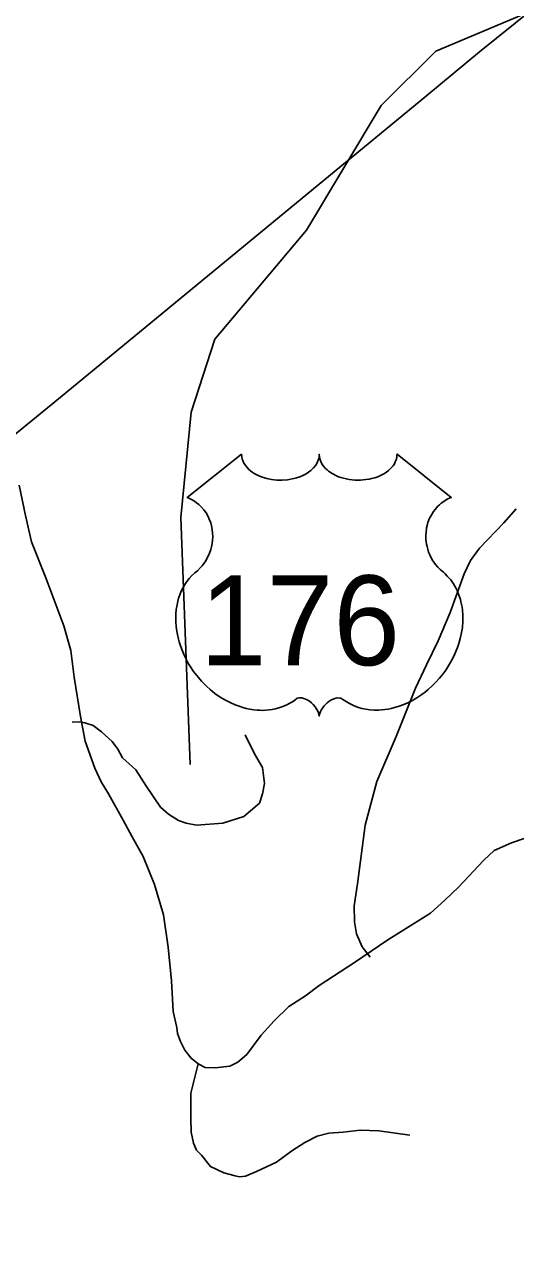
# Model space of a CAD drawing. Extents: x 990631 to 1056237, y 535999 to 585651.
# Drawn here: x 1003300 to 1004463, y 554837 to 557741 of the extents above; entities that cross this region are included whole.
import ezdxf

# ---------------------------------------------------------------- set-up
doc = ezdxf.new("R2010")
doc.units = 0
for name, color, linetype in [('Exist Boundary Political City Limit New', 7, 'Continuous'), ('Exist Hydrographic Creek Single Shore', 7, 'Continuous'), ('Exist Road Non-System Type 51', 7, 'Continuous'), ('Exist Road Primary US Attributed', 7, 'Continuous'), ('Exist Road Primary US Shield CELL', 7, 'Continuous'), ('Exist Road Primary US Shield Number Label', 7, 'Continuous')]:
    doc.layers.add(name, color=color, linetype=linetype)

msp = doc.modelspace()

# ---------------------------------------------------------------- linework, layer by layer
at = {"layer": 'Exist Boundary Political City Limit New'}
msp.add_lwpolyline([(1001301.9, 554778.2), (1001438.1, 555089.9), (1001470.1, 555241.1), (1001552.6, 555419.9), (1001735.9, 555580.4), (1002552.2, 556178.9), (1003398, 556869.2), (1004252.8, 557573.4), (1004377.7, 557676.6), (1005330.6, 558443.4), (1004972.3, 558948.1), (1005102.7, 559003.6), (1005249.3, 559124.2), (1005422, 559391.5), (1005487.1, 559453.4), (1005757.6, 559769.7), (1005899.7, 560044.6), (1005994.2, 560116.4), (1006062.6, 560031.6), (1006189.7, 560148.9), (1006241.8, 560201.1), (1006333.1, 560158.8), (1006620.9, 560644.3), (1006721.9, 560751.9)], dxfattribs=at)
at = {"layer": 'Exist Hydrographic Creek Single Shore'}
msp.add_lwpolyline([(1003692.1, 555990), (1003670, 556574.5), (1003695, 556823.4), (1003750.7, 556996.3), (1003967.8, 557254.5), (1004144.4, 557549.5), (1004273.7, 557678.2), (1005009.6, 557988.3), (1005177.7, 558030.8), (1005469.7, 558038), (1005563.7, 558101.8), (1005642.1, 558198.7), (1005936.2, 558265), (1006174.3, 558407.8), (1006530.5, 558338.3), (1006819.2, 557994.4), (1006909.7, 557956.5), (1007060.2, 557969.9), (1007340.5, 558125.1), (1007600, 558402), (1007761.6, 558497.2), (1008013.6, 558676.5), (1008218.4, 558820.1)], dxfattribs=at)
msp.add_lwpolyline([(1003692.1, 555990), (1003670, 556574.5), (1003695, 556823.4), (1003750.7, 556996.3), (1003967.8, 557254.5), (1004144.4, 557549.5), (1004273.7, 557678.2), (1005009.6, 557988.3), (1005177.7, 558030.8), (1005469.7, 558038), (1005563.7, 558101.8), (1005642.1, 558198.7), (1005936.2, 558265), (1006174.3, 558407.8), (1006530.5, 558338.3), (1006819.2, 557994.4), (1006909.7, 557956.5), (1007060.2, 557969.9), (1007340.5, 558125.1), (1007600, 558402), (1007761.6, 558497.2), (1008013.6, 558676.5), (1008218.4, 558820.1)], dxfattribs=at)
at = {"layer": 'Exist Road Non-System Type 51'}
for points in [[(1004464.2, 556594.9), (1004435.2, 556561.7), (1004377.1, 556501.6), (1004356.1, 556472.2), (1004341.1, 556440.7), (1004308.1, 556349.8), (1004279.7, 556282.7), (1004251.9, 556225.7), (1004226, 556170.4), (1004180.1, 556055.8), (1004134.5, 555949.3), (1004107, 555846.3), (1004088.4, 555706.8), (1004080.8, 555654.9), (1004081.4, 555616.9), (1004086.5, 555588.8), (1004099.4, 555558.3), (1004118.7, 555533.5)], [(1003822.1, 556059.9), (1003844.6, 556015), (1003863.5, 555982.4), (1003868.2, 555944.3), (1003863.5, 555920.4), (1003856.6, 555898.5), (1003819.7, 555866.5), (1003769.7, 555850.7), (1003707, 555846.3), (1003683.1, 555851), (1003664.5, 555856.9), (1003640.8, 555871.8), (1003622.3, 555888.5), (1003589, 555937.6), (1003563.6, 555977.1), (1003532.1, 556005.5), (1003520.7, 556025.9), (1003507.3, 556044.4), (1003482.1, 556067.1), (1003462.6, 556081.9), (1003442.7, 556088.5), (1003430.8, 556091), (1003412.8, 556089.5)], [(1003711, 555281.1), (1003693.7, 555211.6), (1003693.7, 555151.6), (1003694.7, 555119.5), (1003699.8, 555093.2), (1003707.2, 555077.1), (1003718.8, 555064.6), (1003740, 555037.8), (1003771.6, 555022.8), (1003799.2, 555016), (1003809.2, 555013.6), (1003823.2, 555015.1), (1003849.6, 555026.2), (1003896.3, 555048.6), (1003933.3, 555075.5), (1003964.1, 555094.5), (1003992.6, 555109.5), (1004020.7, 555116.6), (1004054.8, 555119.5), (1004095.1, 555124.1), (1004139.1, 555122.6), (1004212.7, 555112.1)]]:
    msp.add_lwpolyline(points, dxfattribs=at)
at = {"layer": 'Exist Road Primary US Attributed'}
msp.add_lwpolyline([(1003287.2, 556650.9), (1003302.1, 556579.2), (1003316.3, 556516.7), (1003350.4, 556431.7), (1003393.4, 556317.6), (1003410, 556259.7), (1003417.9, 556196.1), (1003432.9, 556103), (1003443.4, 556045.1), (1003466.2, 555980.6), (1003481.1, 555949), (1003498.8, 555920.4), (1003533.7, 555857.7), (1003554.8, 555818.2), (1003581.1, 555771.7), (1003608.1, 555705.9), (1003628.8, 555633.9), (1003639.9, 555557.6), (1003648.2, 555477.6), (1003652.2, 555405.1), (1003660.9, 555366.9), (1003662.4, 555352.9), (1003669.7, 555333.8), (1003679.4, 555313.6), (1003694.3, 555294.3), (1003711, 555281.1), (1003727.8, 555272.5), (1003751.8, 555271.6), (1003786.4, 555275.6), (1003804.8, 555285.1), (1003826.8, 555303.5), (1003860.1, 555349.2), (1003890.8, 555382.5), (1003925.9, 555416.7), (1003965.4, 555442.2), (1003997.8, 555466.3), (1004081.2, 555520.7), (1004160.1, 555574.3), (1004261, 555637.5), (1004295.2, 555668.2), (1004327.7, 555699.3), (1004387.4, 555763.4), (1004411.9, 555786.2), (1004453.2, 555804.6), (1004483, 555814.3)], dxfattribs=at)
at = {"layer": 'Exist Road Primary US Shield CELL'}
msp.add_lwpolyline([(1003814, 556724), (1003814.4, 556718.6), (1003815.7, 556712.3), (1003816.7, 556709.1), (1003819.6, 556702.8), (1003824.5, 556695.5), (1003831.3, 556688.3), (1003839, 556681.9), (1003844.1, 556678.6), (1003852.9, 556673.9), (1003862.8, 556669.7), (1003873.9, 556666.5), (1003885.2, 556664.2), (1003897.6, 556662.9), (1003909.8, 556662.6), (1003923.1, 556663.6), (1003937.6, 556666.4), (1003944.4, 556668.2), (1003951.9, 556670.8), (1003958.9, 556673.7), (1003966.6, 556677.8), (1003972.7, 556681.7), (1003977.6, 556685.2), (1003984.4, 556691.7), (1003989.8, 556698.5), (1003992.1, 556702.3), (1003994.1, 556706), (1003996.8, 556713.7), (1003997.5, 556717.1), (1003998.1, 556724.2), (1003998.5, 556718.3), (1003999.1, 556714.5), (1004000.1, 556710.9), (1004001.6, 556707), (1004004.4, 556701.6), (1004007.4, 556697), (1004013.1, 556690.2), (1004016.7, 556686.9), (1004020, 556684.2), (1004028.7, 556678.2), (1004038.9, 556673.1), (1004043.9, 556670.9), (1004049.1, 556669), (1004055.6, 556667.1), (1004062.4, 556665.5), (1004069.1, 556664.3), (1004075.9, 556663.3), (1004082.9, 556662.8), (1004088.6, 556662.6), (1004095.6, 556662.7), (1004102, 556663.1), (1004108.6, 556663.9), (1004115.9, 556665.1), (1004121.8, 556666.4), (1004129.5, 556668.4), (1004136.5, 556670.9), (1004142.7, 556673.6), (1004150.6, 556677.8), (1004157.1, 556681.8), (1004161.8, 556685.6), (1004167.4, 556690.8), (1004172.7, 556696.9), (1004175.9, 556701.4), (1004178.1, 556706), (1004180.1, 556710.9), (1004181.4, 556716.1), (1004182, 556720.5), (1004182.1, 556724.4), (1004310.7, 556621.9), (1004307.7, 556620.8), (1004300.7, 556617.4), (1004295.1, 556614.1), (1004286.3, 556607.9), (1004282.5, 556604.4), (1004278.7, 556600.9), (1004275.2, 556597.1), (1004272.1, 556593.5), (1004268.4, 556588.3), (1004265.1, 556583.2), (1004261.8, 556577.5), (1004259.4, 556572.5), (1004255.4, 556562.2), (1004253.5, 556555.7), (1004252.3, 556550.1), (1004250.8, 556538.6), (1004250.4, 556533.2), (1004250.4, 556527.8), (1004250.7, 556522.1), (1004251.3, 556516.6), (1004252.3, 556510.9), (1004253.2, 556505.9), (1004254.8, 556499.7), (1004257, 556492.6), (1004259.9, 556485.7), (1004265.7, 556474.5), (1004273.3, 556463.1), (1004278.7, 556456.7), (1004284, 556451.3), (1004291.9, 556444.6), (1004296.2, 556440.8), (1004301.2, 556435.8), (1004309.2, 556426.5), (1004312.5, 556422.1), (1004315.8, 556417.1), (1004318.8, 556412), (1004321.9, 556406.6), (1004324.3, 556401.8), (1004328.8, 556390.8), (1004332.1, 556380), (1004333.6, 556374.4), (1004336, 556361.8), (1004336.9, 556355.6), (1004337.9, 556343.3), (1004338, 556328.4), (1004336.8, 556314.2), (1004334.2, 556297.8), (1004332, 556287.9), (1004328.6, 556276.4), (1004325.3, 556266.4), (1004319.4, 556251.8), (1004314.2, 556241.1), (1004307.5, 556228.7), (1004302.8, 556221.2), (1004297.4, 556213.1), (1004290.7, 556203.8), (1004282.8, 556194), (1004273.3, 556183.5), (1004265.6, 556175.9), (1004255.6, 556166.9), (1004249.5, 556161.9), (1004240.9, 556155.4), (1004229, 556147.5), (1004217.3, 556140.7), (1004207.4, 556135.6), (1004198.6, 556131.8), (1004187.2, 556127.5), (1004168.2, 556122.2), (1004161.3, 556120.8), (1004153.1, 556119.6), (1004145.4, 556118.8), (1004138, 556118.4), (1004127.9, 556118.4), (1004118, 556119.1), (1004108.6, 556120.5), (1004098.8, 556122.5), (1004088.5, 556125.6), (1004079.2, 556129.2), (1004069.8, 556133.9), (1004053.9, 556143.9), (1004049.3, 556146.3), (1004046.7, 556147), (1004040.6, 556147.3), (1004034.8, 556146.1), (1004028.9, 556143.7), (1004025.3, 556141.8), (1004020.5, 556138.7), (1004016.9, 556135.8), (1004012.5, 556131.6), (1004009.5, 556128.2), (1004007.1, 556125.4), (1004002.7, 556118.4), (1004001.1, 556115), (1003999.4, 556110.7), (1003997.9, 556104.3), (1003995.9, 556112.3), (1003993.5, 556117.7), (1003990.8, 556122.2), (1003988, 556126.3), (1003983.5, 556131.4), (1003979.5, 556135.3), (1003974.6, 556139.2), (1003969.4, 556142.4), (1003965.3, 556144.5), (1003961.5, 556145.9), (1003956.9, 556147.1), (1003953.1, 556147.4), (1003950, 556147.3), (1003945.7, 556146.3), (1003939.8, 556142.1), (1003934.3, 556138.3), (1003928.3, 556134.6), (1003921.2, 556130.8), (1003916, 556128.4), (1003909.7, 556125.9), (1003902.4, 556123.5), (1003894.5, 556121.5), (1003886.4, 556119.9), (1003879.3, 556118.7), (1003871.6, 556118), (1003864.7, 556117.8), (1003857.5, 556117.9), (1003850.7, 556118.4), (1003842.9, 556119.1), (1003833.2, 556120.6), (1003825.1, 556122.4), (1003816.6, 556124.7), (1003807.9, 556127.4), (1003798.6, 556131), (1003786.9, 556136.1), (1003778.7, 556140.2), (1003765.9, 556147.6), (1003750.9, 556158), (1003739.5, 556167.2), (1003731.2, 556174.7), (1003719, 556187.2), (1003711.8, 556195.3), (1003700.5, 556209.9), (1003693.3, 556220.5), (1003688.6, 556228.2), (1003681.8, 556240.7), (1003678, 556248.5), (1003673.2, 556259.9), (1003669.3, 556270.3), (1003666.1, 556280.2), (1003664.4, 556286.5), (1003662, 556297.5), (1003660.5, 556305.4), (1003659.1, 556316.1), (1003658.3, 556327.4), (1003658.1, 556337.8), (1003658.4, 556346.5), (1003659.4, 556356.6), (1003661.1, 556367.3), (1003663.1, 556376.5), (1003665, 556383.1), (1003667.7, 556391.1), (1003671.3, 556400), (1003675.6, 556408.5), (1003679.7, 556415.6), (1003684.7, 556423.2), (1003689.8, 556429.7), (1003696.3, 556436.8), (1003703.2, 556443.3), (1003709.4, 556448.4), (1003716.9, 556455.7), (1003720.8, 556460.1), (1003725.4, 556466.3), (1003729.1, 556472), (1003732.1, 556477.1), (1003736, 556484.6), (1003738.4, 556490.2), (1003741.3, 556498.9), (1003742.8, 556505), (1003744.3, 556512.8), (1003745.3, 556520.2), (1003745.7, 556529.4), (1003745.5, 556537), (1003744.5, 556545.8), (1003742.8, 556554.4), (1003740.8, 556561.8), (1003737.6, 556570.3), (1003734.7, 556576.5), (1003729.8, 556585), (1003724.3, 556592.8), (1003718.6, 556599.2), (1003712.9, 556604.9), (1003707.5, 556609.1), (1003702.3, 556612.9), (1003695.7, 556616.8), (1003689.4, 556619.9), (1003685.5, 556621.5)], close=True, dxfattribs=at)
msp.add_lwpolyline([(1003814, 556724), (1003814.4, 556718.6), (1003815.7, 556712.3), (1003816.7, 556709.1), (1003819.6, 556702.8), (1003824.5, 556695.5), (1003831.3, 556688.3), (1003839, 556681.9), (1003844.1, 556678.6), (1003852.9, 556673.9), (1003862.8, 556669.7), (1003873.9, 556666.5), (1003885.2, 556664.2), (1003897.6, 556662.9), (1003909.8, 556662.6), (1003923.1, 556663.6), (1003937.6, 556666.4), (1003944.4, 556668.2), (1003951.9, 556670.8), (1003958.9, 556673.7), (1003966.6, 556677.8), (1003972.7, 556681.7), (1003977.6, 556685.2), (1003984.4, 556691.7), (1003989.8, 556698.5), (1003992.1, 556702.3), (1003994.1, 556706), (1003996.8, 556713.7), (1003997.5, 556717.1), (1003998.1, 556724.2), (1003998.5, 556718.3), (1003999.1, 556714.5), (1004000.1, 556710.9), (1004001.6, 556707), (1004004.4, 556701.6), (1004007.4, 556697), (1004013.1, 556690.2), (1004016.7, 556686.9), (1004020, 556684.2), (1004028.7, 556678.2), (1004038.9, 556673.1), (1004043.9, 556670.9), (1004049.1, 556669), (1004055.6, 556667.1), (1004062.4, 556665.5), (1004069.1, 556664.3), (1004075.9, 556663.3), (1004082.9, 556662.8), (1004088.6, 556662.6), (1004095.6, 556662.7), (1004102, 556663.1), (1004108.6, 556663.9), (1004115.9, 556665.1), (1004121.8, 556666.4), (1004129.5, 556668.4), (1004136.5, 556670.9), (1004142.7, 556673.6), (1004150.6, 556677.8), (1004157.1, 556681.8), (1004161.8, 556685.6), (1004167.4, 556690.8), (1004172.7, 556696.9), (1004175.9, 556701.4), (1004178.1, 556706), (1004180.1, 556710.9), (1004181.4, 556716.1), (1004182, 556720.5), (1004182.1, 556724.4), (1004310.7, 556621.9), (1004307.7, 556620.8), (1004300.7, 556617.4), (1004295.1, 556614.1), (1004286.3, 556607.9), (1004282.5, 556604.4), (1004278.7, 556600.9), (1004275.2, 556597.1), (1004272.1, 556593.5), (1004268.4, 556588.3), (1004265.1, 556583.2), (1004261.8, 556577.5), (1004259.4, 556572.5), (1004255.4, 556562.2), (1004253.5, 556555.7), (1004252.3, 556550.1), (1004250.8, 556538.6), (1004250.4, 556533.2), (1004250.4, 556527.8), (1004250.7, 556522.1), (1004251.3, 556516.6), (1004252.3, 556510.9), (1004253.2, 556505.9), (1004254.8, 556499.7), (1004257, 556492.6), (1004259.9, 556485.7), (1004265.7, 556474.5), (1004273.3, 556463.1), (1004278.7, 556456.7), (1004284, 556451.3), (1004291.9, 556444.6), (1004296.2, 556440.8), (1004301.2, 556435.8), (1004309.2, 556426.5), (1004312.5, 556422.1), (1004315.8, 556417.1), (1004318.8, 556412), (1004321.9, 556406.6), (1004324.3, 556401.8), (1004328.8, 556390.8), (1004332.1, 556380), (1004333.6, 556374.4), (1004336, 556361.8), (1004336.9, 556355.6), (1004337.9, 556343.3), (1004338, 556328.4), (1004336.8, 556314.2), (1004334.2, 556297.8), (1004332, 556287.9), (1004328.6, 556276.4), (1004325.3, 556266.4), (1004319.4, 556251.8), (1004314.2, 556241.1), (1004307.5, 556228.7), (1004302.8, 556221.2), (1004297.4, 556213.1), (1004290.7, 556203.8), (1004282.8, 556194), (1004273.3, 556183.5), (1004265.6, 556175.9), (1004255.6, 556166.9), (1004249.5, 556161.9), (1004240.9, 556155.4), (1004229, 556147.5), (1004217.3, 556140.7), (1004207.4, 556135.6), (1004198.6, 556131.8), (1004187.2, 556127.5), (1004168.2, 556122.2), (1004161.3, 556120.8), (1004153.1, 556119.6), (1004145.4, 556118.8), (1004138, 556118.4), (1004127.9, 556118.4), (1004118, 556119.1), (1004108.6, 556120.5), (1004098.8, 556122.5), (1004088.5, 556125.6), (1004079.2, 556129.2), (1004069.8, 556133.9), (1004053.9, 556143.9), (1004049.3, 556146.3), (1004046.7, 556147), (1004040.6, 556147.3), (1004034.8, 556146.1), (1004028.9, 556143.7), (1004025.3, 556141.8), (1004020.5, 556138.7), (1004016.9, 556135.8), (1004012.5, 556131.6), (1004009.5, 556128.2), (1004007.1, 556125.4), (1004002.7, 556118.4), (1004001.1, 556115), (1003999.4, 556110.7), (1003997.9, 556104.3), (1003995.9, 556112.3), (1003993.5, 556117.7), (1003990.8, 556122.2), (1003988, 556126.3), (1003983.5, 556131.4), (1003979.5, 556135.3), (1003974.6, 556139.2), (1003969.4, 556142.4), (1003965.3, 556144.5), (1003961.5, 556145.9), (1003956.9, 556147.1), (1003953.1, 556147.4), (1003950, 556147.3), (1003945.7, 556146.3), (1003939.8, 556142.1), (1003934.3, 556138.3), (1003928.3, 556134.6), (1003921.2, 556130.8), (1003916, 556128.4), (1003909.7, 556125.9), (1003902.4, 556123.5), (1003894.5, 556121.5), (1003886.4, 556119.9), (1003879.3, 556118.7), (1003871.6, 556118), (1003864.7, 556117.8), (1003857.5, 556117.9), (1003850.7, 556118.4), (1003842.9, 556119.1), (1003833.2, 556120.6), (1003825.1, 556122.4), (1003816.6, 556124.7), (1003807.9, 556127.4), (1003798.6, 556131), (1003786.9, 556136.1), (1003778.7, 556140.2), (1003765.9, 556147.6), (1003750.9, 556158), (1003739.5, 556167.2), (1003731.2, 556174.7), (1003719, 556187.2), (1003711.8, 556195.3), (1003700.5, 556209.9), (1003693.3, 556220.5), (1003688.6, 556228.2), (1003681.8, 556240.7), (1003678, 556248.5), (1003673.2, 556259.9), (1003669.3, 556270.3), (1003666.1, 556280.2), (1003664.4, 556286.5), (1003662, 556297.5), (1003660.5, 556305.4), (1003659.1, 556316.1), (1003658.3, 556327.4), (1003658.1, 556337.8), (1003658.4, 556346.5), (1003659.4, 556356.6), (1003661.1, 556367.3), (1003663.1, 556376.5), (1003665, 556383.1), (1003667.7, 556391.1), (1003671.3, 556400), (1003675.6, 556408.5), (1003679.7, 556415.6), (1003684.7, 556423.2), (1003689.8, 556429.7), (1003696.3, 556436.8), (1003703.2, 556443.3), (1003709.4, 556448.4), (1003716.9, 556455.7), (1003720.8, 556460.1), (1003725.4, 556466.3), (1003729.1, 556472), (1003732.1, 556477.1), (1003736, 556484.6), (1003738.4, 556490.2), (1003741.3, 556498.9), (1003742.8, 556505), (1003744.3, 556512.8), (1003745.3, 556520.2), (1003745.7, 556529.4), (1003745.5, 556537), (1003744.5, 556545.8), (1003742.8, 556554.4), (1003740.8, 556561.8), (1003737.6, 556570.3), (1003734.7, 556576.5), (1003729.8, 556585), (1003724.3, 556592.8), (1003718.6, 556599.2), (1003712.9, 556604.9), (1003707.5, 556609.1), (1003702.3, 556612.9), (1003695.7, 556616.8), (1003689.4, 556619.9), (1003685.5, 556621.5)], close=True, dxfattribs=at)

# ---------------------------------------------------------------- texts
at = {"layer": 'Exist Road Primary US Shield Number Label'}
msp.add_text('176', height=212.5, dxfattribs=at).set_placement((1003715.2, 556224.7))
msp.add_text('176', height=212.5, dxfattribs=at).set_placement((1003715.2, 556224.7))

doc.saveas('drawing.dxf')
